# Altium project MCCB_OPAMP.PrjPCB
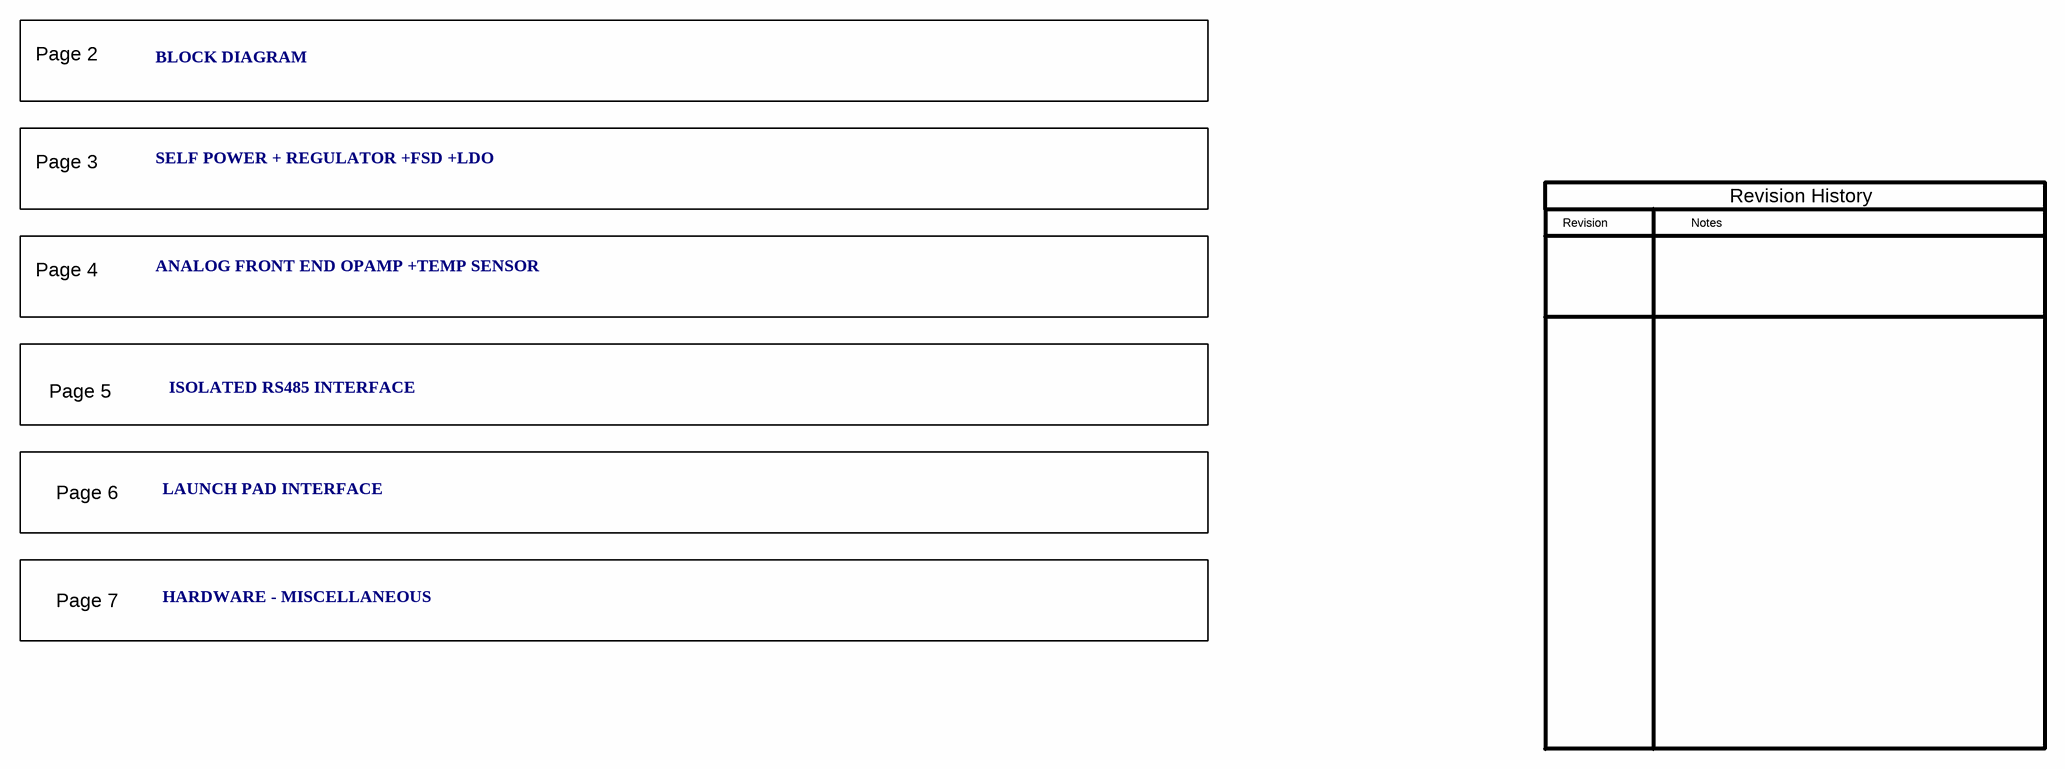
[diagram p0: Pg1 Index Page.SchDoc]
CopyrightYear: 2013; PCB_Layout: Who did the Layout?; PCB_Rev: E2; PRJ_Customer: Public Release; PRJ_Engineer: Enter name of project lead; PRJ_Number: TIDA-00128; PRJ_Title: TIDA-00128 OPAMP BASED MCCB ETU; SCH_Rev: E2; TechSupport: http://www.ti.com/support
7 sheets, 239 parts. Net scope: flat (ports and power ports of the same name join across sheets).
Board file: MCCB_OPAMP.PcbDoc
Sheets:
  Pg1 Index Page.SchDoc
  Pg2 Block Diagram.SchDoc
  Pg3.SchDoc
  Pg4.SchDoc
  Pg5.SchDoc
  Pg6.SchDoc
  Pg7 Hardware.SchDoc

## Sheet Pg1 Index Page.SchDoc
size 431 x 279 mm; Date: Not shown in title block; ApprovedBy: Not shown in title block; CheckedBy: Not shown in title block; Author: Not shown in title block; CompanyName: Not shown in title block; Engineer: Not shown in title block; Organization: Not shown in title block; Address1: Not shown in title block; Address2: Not shown in title block; Address3: Not shown in title block; Address4: Not shown in title block; DocumentNumber: 1; Revision: Use project parameter SCH_Rev; SheetNumber: 1; SheetTotal: 7; PageSetup: Record=PageOptions|CenterHorizontal=True|CenterVertical=True|PrintScale=1.00|XCorrection=1.00|YCorrection=1.00|PrintKind=0|BorderSize=5000000|LeftOffset=0|BottomOffset=0|Orientation=2|PaperLength=1000|PaperWidth=1000|Scale=100|PaperSource=15|PrintQuality=600|MediaType=1|DitherType=10|PaperKind=Letter|PrintScaleMode=1

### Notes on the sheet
- Page 2
- BLOCK DIAGRAM
- Page 3
- SELF POWER + REGULATOR +FSD +LDO
- Revision
- Notes
- Revision History
- Page 4
- ANALOG FRONT END OPAMP +TEMP SENSOR
- Page 5
- ISOLATED RS485 INTERFACE
- Page 6
- LAUNCH PAD INTERFACE
- Page 7
- HARDWARE - MISCELLANEOUS

## Sheet Pg2 Block Diagram.SchDoc
size 431 x 279 mm; Date: Not shown in title block; ApprovedBy: Not shown in title block; CheckedBy: Not shown in title block; Author: Not shown in title block; CompanyName: Not shown in title block; Engineer: Not shown in title block; Organization: Not shown in title block; Address1: Not shown in title block; Address2: Not shown in title block; Address3: Not shown in title block; Address4: Not shown in title block; DocumentNumber: 2; Revision: Use project parameter SCH_Rev; SheetNumber: 2; SheetTotal: 7; PageSetup: Record=PageOptions|CenterHorizontal=True|CenterVertical=True|PrintScale=1.00|XCorrection=1.00|YCorrection=1.00|PrintKind=0|BorderSize=5000000|LeftOffset=0|BottomOffset=0|Orientation=2|PaperLength=1000|PaperWidth=1000|Scale=100|PaperSource=15|PrintQuality=600|MediaType=1|DitherType=10|PaperKind=Letter|PrintScaleMode=1
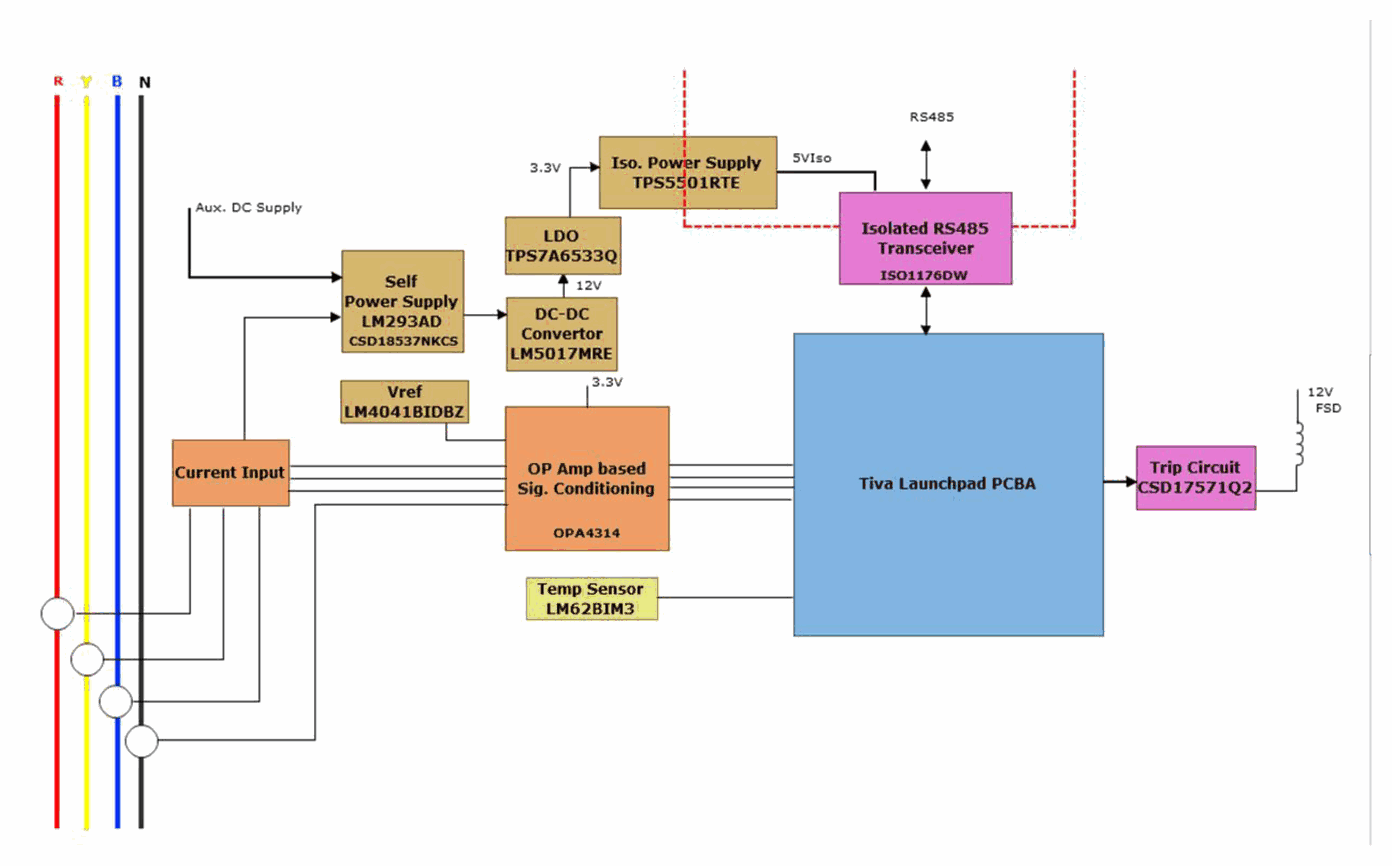
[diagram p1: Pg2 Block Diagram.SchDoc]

## Sheet Pg3.SchDoc
size 431 x 279 mm; Date: Not shown in title block; ApprovedBy: Not shown in title block; CheckedBy: Not shown in title block; Author: Not shown in title block; CompanyName: Not shown in title block; Engineer: Not shown in title block; Organization: Not shown in title block; Address1: Not shown in title block; Address2: Not shown in title block; Address3: Not shown in title block; Address4: Not shown in title block; DocumentNumber: 3; Revision: Use project parameter SCH_Rev; SheetNumber: 3; SheetTotal: 7; PageSetup: Record=PageOptions|CenterHorizontal=True|CenterVertical=True|PrintScale=1.00|XCorrection=1.00|YCorrection=1.00|PrintKind=0|BorderSize=5000000|LeftOffset=0|BottomOffset=0|Orientation=2|PaperLength=1000|PaperWidth=1000|Scale=100|PaperSource=15|PrintQuality=600|MediaType=1|DitherType=10|PaperKind=Letter|PrintScaleMode=1
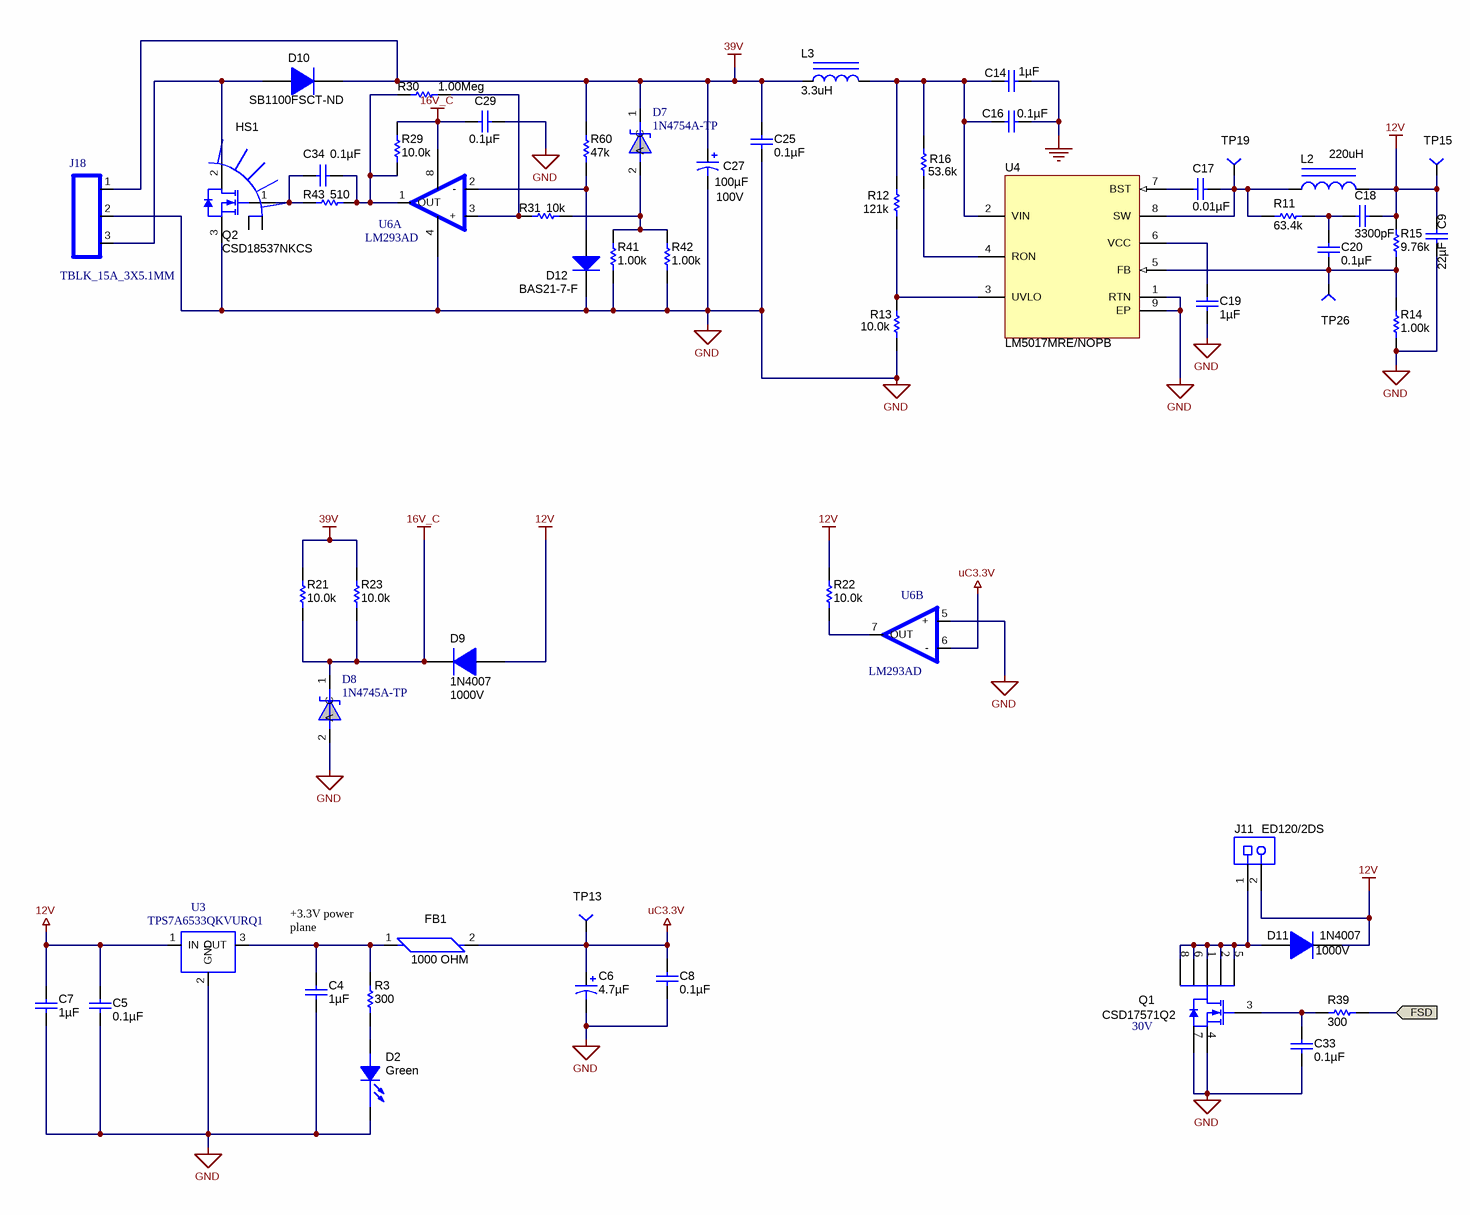
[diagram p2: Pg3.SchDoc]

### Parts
C4  ValueDisplayed: 1µF  [0603]  (hidden comment: C1608X7R1C105K)
C5  ValueDisplayed: 0.1µF  [0603]  (hidden comment: C0603C104K5RACTU)
C6  ValueDisplayed: 4.7µF  [6032-28]  (hidden comment: 293D475X9035C2TE3)
C7  ValueDisplayed: 1µF  [0603]  (hidden comment: C1608X7R1C105K)
C8  ValueDisplayed: 0.1µF  [0603]  (hidden comment: C0603C104K5RACTU)
C9  ValueDisplayed: 22µF  [1206]  (hidden comment: GRM31CR61C226KE15L)
C14  ValueDisplayed: 1µF  [1206]  (hidden comment: GRM31CR72A105KA01L)
C16  ValueDisplayed: 0.1µF  [0805_HV]  (hidden comment: C0805C104K1RACTU)
C17  ValueDisplayed: 0.01µF  [0603]  (hidden comment: C1608C0G1E103J)
C18  ValueDisplayed: 3300pF  [0603]  (hidden comment: C0603C332K5RACTU)
C19  ValueDisplayed: 1µF  [0603]  (hidden comment: C1608X5R1E105K080AC)
C20  ValueDisplayed: 0.1µF  [0603]  (hidden comment: 06033C104JAT2A)
C25  ValueDisplayed: 0.1µF  [0805_HV]  (hidden comment: C0805C104K1RACTU)
C27  ValueDisplayed: 100µF  Value2: 100V  [YXJ_1000x2000]  (hidden comment: 100YXJ100M10X20)
C29  ValueDisplayed: 0.1µF  [0603]  (hidden comment: C0603C104K5RACTU)
C33  ValueDisplayed: 0.1µF  [0603]  (hidden comment: 06033C104JAT2A)
C34  ValueDisplayed: 0.1µF  [0603]  (hidden comment: 06033C104JAT2A)
D2  value Green  [LED0603AA]  (hidden comment: LED_LG L29K-G2J1-24-Z)
D7  1N4754A-TP  [DO-41]
D8  1N4745A-TP  [DO-41]
D9  1N4007  value 1000V  [DO-41]
D10  SB1100FSCT-ND  [DO-41]
D11  1N4007  value 1000V  [DO-41]
D12  BAS21-7-F  [SOT-23]
FB1  1000 OHM  [0603]
HS1  HEATSINK_513102B02500G  [HEATSINK_513201]  (value not drawn)
J11  ED120/2DS  [CONN_ED120-2DS]
J18  TBLK_15A_3X5.1MM  [TB_3X5.1MM]
L2  value 220uH  [SRR7045]  (hidden comment: SRR7032-221M)
L3  value 3.3uH  [1210]  (hidden comment: B82422H1332K)
Q1  CSD17571Q2  value 30V  [SON_CSD17571Q2]
Q2  CSD18537NKCS  [TO-220AB]
R3  value 300  [0603]  (hidden comment: CRCW0603300RJNEA)
R11  value 63.4k  [0603]  (hidden comment: CRCW060363K4FKEA)
R12  value 121k  [0805_HV]  (hidden comment: RT0805BRD07121KL)
R13  value 10.0k  [0603]  (hidden comment: CRCW060310K0FKEA)
R14  value 1.00k  [0603]  (hidden comment: RC0603FR-071KL)
R15  value 9.76k  [0603]  (hidden comment: CRCW06039K76FKEA)
R16  value 53.6k  [0805_HV]  (hidden comment: RG2012P-5362-B-T5)
R21  value 10.0k  [1206]  (hidden comment: CRCW120610K0FKEA)
R22  value 10.0k  [0603]  (hidden comment: CRCW060310K0FKEA)
R23  value 10.0k  [1206]  (hidden comment: CRCW120610K0FKEA)
R29  value 10.0k  [1206]  (hidden comment: CRCW120610K0FKEA)
R30  value 1.00Meg  [0603]  (hidden comment: CRCW06031M00FKEA)
R31  value 10k  [0603]  (hidden comment: RNCF0603TKY10K0)
R39  value 300  [0603]  (hidden comment: CRCW0603300RJNEA)
R41  value 1.00k  [1206]  (hidden comment: CRCW12061K00FKEA)
R42  value 1.00k  [1206]  (hidden comment: CRCW12061K00FKEA)
R43  value 510  [0603]  (hidden comment: RG1608P-511-B-T5)
R60  value 47k  [0805_HV]  (hidden comment: ERJ-6GEYJ473V)
TP13  TP-040_RND  [TP-040_RND]  (value not drawn)
TP15  TP-040_RND  [TP-040_RND]  (value not drawn)
TP19  TP-040_RND  [TP-040_RND]  (value not drawn)
TP26  TP-040_RND  [TP-040_RND]  (value not drawn)
U3  TPS7A6533QKVURQ1  [KVU_1]
U4  LM5017MRE/NOPB  [DDA0008B_N]
U6  LM293AD  [SO8]  (parts A,B of 2)

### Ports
FSD (in)

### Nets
12V: C5.1 C7.1 C9.1 C18.1 D9.2(A) D11.1(K) J11.2 L2.2 R15.2 R22.2 TP15.1 U3.1(IN)
16V_C: C29.1 D8.1(C) D9.1(K) R21.1 R23.1 R29.1 U6.8(VCC)
39V: C25.1 C27.1(+) D7.1(C) D10.1(K) J18.1 L3.1 R21.2 R23.2 R60.2
GND: C4.2 C5.2 C6.2(-) C7.2 C8.2 C9.2 C14.1 C16.1 C19.2 C25.2 C27.2(-) C29.2 C33.2 D2.1(C) D8.2(A) D12.3(K) J18.2 Q1.4(S) Q1.7(S) Q2.3(S) R13.1 R14.1 R41.1 R42.1 U3.2(GND) U4.1(RTN) U4.9(EP) U6.4(GND) U6.5(+)
uC3.3V: C6.1(+) C8.1 FB1.2 TP13.1 U6.6(-)
FSD: R39.1 ; port FSD
NetC4_1: C4.1 FB1.1 R3.2 U3.3(OUT)
NetC14_2: C14.2 C16.2 L3.2 R12.2 R16.2 U4.2(VIN)
NetC17_1: C17.1 U4.7(BST)
NetC17_2: C17.2 L2.1 R11.1 TP19.1 U4.8(SW)
NetC18_2: C18.2 C20.2 R11.2
NetC19_1: C19.1 U4.6(VCC)
NetC20_1: C20.1 R14.2 R15.1 TP26.1 U4.5(FB)
NetC33_1: C33.1 Q1.3(G) R39.2
NetC34_1: C34.1 R29.2 R30.2 R43.1 U6.1(OUT)
NetC34_2: C34.2 Q2.1(G) R43.2
NetD2_2: D2.2(A) R3.1
NetD7_2: D7.2(A) R31.2 R41.2 R42.2
NetD10_2: D10.2(A) J18.3 Q2.2(D)
NetD11_2: D11.2(A) J11.1 Q1.1(D) Q1.2(D) Q1.5(D) Q1.6(D) Q1.8(D)
NetD12_1: D12.1(A) R60.1 U6.2(-)
NetR12_1: R12.1 R13.2 U4.3(UVLO)
NetR16_1: R16.1 U4.4(RON)
NetR22_1: R22.1 U6.7(OUT)
NetR30_1: R30.1 R31.1 U6.3(+)

Not connected (* = marked no-connect by the designer): HS1 1 2

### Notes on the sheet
- (near FB1) +3.3V power
  plane

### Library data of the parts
C4 C7 = C1608X7R1C105K: CAP, CERM, 1uF, 16V, +/-10%, X7R, 0603; Manufacturer: TDK; Polarized: N; CompType: Capacitor; U/M: EA; Cap_F: 0.000001; Tolerance_%: 10; ESR_Ohm: 0.0057; Value1: 0.0057 ohm; VDC_V: 16; TaMin_C: -55; TaMax_C: 125
C5 C8 C29 = C0603C104K5RACTU: CAP, CERM, 0.1uF, 50V, +/-10%, X7R, 0603; Manufacturer: Kemet; Polarized: N; CompType: Capacitor; U/M: EA; Cap_F: 0.0000001; Tolerance_%: 10; Value1: Unknown; VDC_V: 50; TaMin_C: -55; TaMax_C: 125
C6 = 293D475X9035C2TE3: CAP, TA, 4.7uF, 35V, +/-10%, 1.9 ohm, SMD; Manufacturer: Vishay-Sprague; Polarized: Y; CompType: Capacitor; U/M: EA; Cap_F: 0.0000047; Tolerance_%: 10; Value1: 1.9 ohm; VDC_V: 35; ESR_Ohm: 1.9; IRMS_A: 0.24; TaMin_C: -55; TaMax_C: 125; Cap_Case: C
C9 = GRM31CR61C226KE15L: CAP, CERM, 22uF, 16V, +/-10%, X5R, 1206; Manufacturer: MuRata; Polarized: N; CompType: Capacitor; U/M: EA; Cap_F: 0.000022; Tolerance_%: 10; Value1: Unknown; VDC_V: 16; TaMin_C: -55; TaMax_C: 85
C14 = GRM31CR72A105KA01L: CAP, CERM, 1uF, 100V, +/-10%, X7R, 1206; Manufacturer: MuRata; Polarized: N; CompType: Capacitor; U/M: EA; Cap_F: 0.000001; Tolerance_%: 10; Value1: Unknown; VDC_V: 100; TaMin_C: -55; TaMax_C: 125; Cap_Case: 2220
C16 C25 = C0805C104K1RACTU: CAP, CERM, 0.1uF, 100V, +/-10%, X7R, 0805; Manufacturer: Kemet; Polarized: N; CompType: Capacitor; U/M: EA; Cap_F: 0.0000001; Tolerance_%: 10; ESR_Ohm: 0.064; Value1: 0.064 ohm; VDC_V: 100; IRMS_A: 1.64; TaMin_C: -55; TaMax_C: 125; Cap_Case: 0805
C17 = C1608C0G1E103J: CAP, CERM, 0.01uF, 25V, +/-5%, C0G/NP0, 0603; Manufacturer: TDK; Polarized: N; CompType: Capacitor; U/M: EA; Cap_F: 0.00000001; Tolerance_%: 5; Value1: Unknown; VDC_V: 25; TaMin_C: -55; TaMax_C: 125
C18 = C0603C332K5RACTU: CAP, CERM, 3300pF, 50V, +/-10%, X7R, 0603; Manufacturer: Kemet; Polarized: N; CompType: Capacitor; U/M: EA; Cap_F: 0.0000000033; Tolerance_%: 10; Value1: Unknown; VDC_V: 50; TaMin_C: -55; TaMax_C: 125
C19 = C1608X5R1E105K080AC: CAP, CERM, 1uF, 25V, +/-10%, X5R, 0603; Manufacturer: TDK; Polarized: N; CompType: Capacitor; U/M: EA; Cap_F: 0.000001; Tolerance_%: 10; Value1: Unknown; VDC_V: 25; TaMin_C: -55; TaMax_C: 85
C20 C33 C34 = 06033C104JAT2A: CAP, CERM, 0.1uF, 25V, +/-5%, X7R, 0603; Manufacturer: AVX; Polarized: N; CompType: Capacitor; U/M: EA; Cap_F: 0.0000001; Tolerance_%: 5; ESR_Ohm: 0.05; Value1: 0.05 ohm; VDC_V: 25; TaMin_C: -55; TaMax_C: 125
C27 = 100YXJ100M10X20: CAP, AL, 100uF, 100V, +/-20%, 0.12 ohm, TH; Manufacturer: Rubycon; Polarized: Y; CompType: Capacitor; U/M: EA; Cap_F: 0.0001; Tolerance_%: 20; VDC_V: 100; ESR_Ohm: 0.12; IRMS_A: 1.04; TaMin_C: -40; TaMax_C: 105; Cap_Case: 10x20
D2 = LED_LG L29K-G2J1-24-Z: LED SmartLED Green 570NM; Manufacturer: OSRAM; SymbolCreator: x0120606
D7 = 1N4754A-TP: Diode, Zener, 39V, 1W, DO41; Manufacturer: Micro Commercial Co; Area: 54000
D8 = 1N4745A-TP: Diode, Zener, 16V, 1W, DO41; Manufacturer: Micro Commercial Co; Area: 54000
D9 D11 = 1N4007: Diode, P-N, 1000V, 1A, TH; Manufacturer: Fairchild Semiconductor; U/M: EA; Vf_V: 1.1; Value2: 1.1V; Io_A: 1; Vr_V: 1000; TJmax_C: 175; RJC_CperW: 50
D10 = 1N4007: Diode, P-N, 1100V, 1A, TH; Manufacturer: Fairchild Semiconductor; U/M: EA; Vf_V: 1.1; Value2: 1.1V; Io_A: 1; Vr_V: 1000; TJmax_C: 175; RJC_CperW: 50
D12 = BAS21-7-F: Diode, Switching, 200V, 0.2A, SOT-23; Manufacturer: Diodes Inc.; U/M: EA; Vf_V: 1.25; Value2: 1.25V; Io_A: 0.2; Vr_V: 200; TJmax_C: 150; RJC_CperW: 500
FB1 = MMZ1608B102C: FERRITE CHIP 1000 OHM 300MA 0603; Manufacturer: TDK Corporation; CompType: Ferrite Bead
HS1 = HEATSINK_513201: HEATSINK TO-220 W/PINS 1.5"TALL; Manufacturer: Aavid Thermalloy; area: 739800
J11 = ED120/2DS: TERMINAL BLOCK 5.08MM VERT 2POS, TH; Manufacturer: On-Shore Technology; SymbolCreator: a0412235; U/M: EA
J18 = TBLK_15A_3X5.1MM: Terminal Block, 3-pin, 15-A, 5.1mm; Manufacturer: OST; PartNumber: ED120/3DS; area: 212400; Value: ED120/3DS
L2 = IND_SRR7032-221M: Inductor, 220uH .30A SMD; Manufacturer: Bourns; Material: Ferrite
L3 = IND_B82422H1332K: Inductor, Chip, 3.3uH 770MA 1210 10%; Manufacturer: EPCOS Inc; Area: 28000
Q1 = CSD17571Q2: MOSFET, N-CH, 30V, 22A, SON 2X2 MM; Manufacturer: TEXAS INSTRUMENTS; CompType: POWER MOSFET
Q2 = CSD18537NKCS: MOSFET, N-CH, 60V, 50A, TO-220AB; Manufacturer: Texas Instruments; Alternate Manufacturer: None; ChType: N
R3 R39 = CRCW0603300RJNEA: RES, 300 ohm, 5%, 0.1W, 0603; Manufacturer: Vishay-Dale; CompType: Resistor; Value_Code: 300R; Tolerance_%: 5; Power_W: 0.1; VDC_V: 75; TempCo: 200 ppm/C; EIA_Code: E24; U/M: EA
R11 = CRCW060363K4FKEA: RES, 63.4k ohm, 1%, 0.1W, 0603; Manufacturer: Vishay-Dale; CompType: Resistor; Res_ohm: 63400; Value_Code: 63k4; Tolerance_%: 1; Power_W: 0.1; VDC_V: 75; TempCo: 100 ppm/C; EIA_Code: E96; U/M: EA
R12 = RT0805BRD07121KL: RES, 121k ohm, 0.1%, 0.125W, 0805; Manufacturer: Yageo America; CompType: Resistor; Res_ohm: 121000; Tolerance_%: 0.1; Power_W: 0.125; VDC_V: 150; TempCo: 25 ppm/C; EIA_Code: E192; U/M: EA
R13 R22 = CRCW060310K0FKEA: RES, 10.0k ohm, 1%, 0.1W, 0603; Manufacturer: Vishay-Dale; CompType: Resistor; Res_ohm: 10000; Value_Code: 10k0; Tolerance_%: 1; Power_W: 0.1; VDC_V: 75; TempCo: 100 ppm/C; EIA_Code: E96; U/M: EA
R14 = RC0603FR-071KL: RES, 1.00k ohm, 1%, 0.1W, 0603; Manufacturer: Yageo America; CompType: Resistor; Res_ohm: 1000; Value_Code: 1k00; Tolerance_%: 1; Power_W: 0.1; VDC_V: 150; TempCo: 200 ppm/C; EIA_Code: E96; U/M: EA
R15 = CRCW06039K76FKEA: RES, 9.76k ohm, 1%, 0.1W, 0603; Manufacturer: Vishay-Dale; CompType: Resistor; Res_ohm: 9760; Value_Code: 9k76; Tolerance_%: 1; Power_W: 0.1; VDC_V: 75; TempCo: 100 ppm/C; EIA_Code: E96; U/M: EA
R16 = RG2012P-5362-B-T5: RES, 53.6k ohm, 0.1%, 0.125W, 0805; Manufacturer: Susumu Co Ltd; CompType: Resistor; Res_ohm: 53600; Value_Code: 53k6; Tolerance_%: 0.1; Power_W: 0.125; VDC_V: 100; TempCo: 25 ppm/C; EIA_Code: E192; U/M: EA
R21 R23 R29 = CRCW120610K0FKEA: RES, 10.0k ohm, 1%, 0.25W, 1206; Manufacturer: Vishay-Dale; CompType: Resistor; Res_ohm: 10000; Value_Code: 10k0; Tolerance_%: 1; Power_W: 0.25; VDC_V: 200; TempCo: 100 ppm/C; EIA_Code: E96; U/M: EA
R30 = CRCW06031M00FKEA: RES, 1.00Meg ohm, 1%, 0.1W, 0603; Manufacturer: Vishay-Dale; CompType: Resistor; Res_ohm: 1000000; Value_Code: 1M00; Tolerance_%: 1; Power_W: 0.1; VDC_V: 75; TempCo: 100 ppm/C; EIA_Code: E96; U/M: EA
R31 = RNCF0603TKY10K0: RES, 10k ohm, 0.01%, 0.063W, 0603; Manufacturer: Stackpole Electronics Inc; CompType: Resistor; Res_ohm: 10000; Value_Code: 10k0; Tolerance_%: 0.01; Power_W: 0.063; VDC_V: 50; TempCo: 5 ppm/C; U/M: EA
R41 R42 = CRCW12061K00FKEA: RES, 1.00k ohm, 1%, 0.25W, 1206; Manufacturer: Vishay-Dale; CompType: Resistor; Res_ohm: 1000; Value_Code: 1k00; Tolerance_%: 1; Power_W: 0.25; VDC_V: 200; TempCo: 100 ppm/C; EIA_Code: E96; U/M: EA
R43 = RG1608P-511-B-T5: RES, 510 ohm, 0.1%, 0.1W, 0603; Manufacturer: Susumu Co Ltd; CompType: Resistor; Value_Code: 510R; Tolerance_%: 0.1; VDC_V: 75; TempCo: 25 ppm/C; U/M: EA
R60 = ERJ-6GEYJ473V: RES, 47k ohm, 5%, 0.125W, 0805; Manufacturer: Panasonic; CompType: Resistor; Res_ohm: 47000; Value_Code: 47k0; Tolerance_%: 5; Power_W: 0.125; VDC_V: 150; TempCo: 200 ppm/C; EIA_Code: E24; U/M: EA
TP13 TP15 TP19 TP26 = TP-040_RND: Test Point, O.040 Hole; Manufacturer: STD; Value: STD
U3 = TPS7A6533QKVURQ1: IC, 300-mA 40-V LOW-DROPOUT REGULATOR WITH 25-uA QUIESCENT CURRENT; Manufacturer: TI; Alternate Manufacturer: None; Area: 136210
U4 = LM5017MRE/NOPB: 100V, 600mA Constant On-Time Synchronous Buck Regulator, DDA0008B; Alternate Manufacturer: None; Manufacturer: Texas Instruments; SymbolCreator: a0412235; CompType: IC; U/M: EA
U6 = LM293AD: IC, Dual Differential Comparators, 2-36 Vin; Manufacturer: TI; Alternate Manufacturer: None; Area: 75900

## Sheet Pg4.SchDoc
size 431 x 279 mm; Date: Not shown in title block; ApprovedBy: Not shown in title block; CheckedBy: Not shown in title block; Author: Not shown in title block; CompanyName: Not shown in title block; Engineer: Not shown in title block; Organization: Not shown in title block; Address1: Not shown in title block; Address2: Not shown in title block; Address3: Not shown in title block; Address4: Not shown in title block; DocumentNumber: 4; Revision: Use project parameter SCH_Rev; SheetNumber: 4; SheetTotal: 7; PageSetup: Record=PageOptions|CenterHorizontal=True|CenterVertical=True|PrintScale=0.59|XCorrection=1.00|YCorrection=1.00|PrintKind=0|BorderSize=5000000|LeftOffset=0|BottomOffset=0|Orientation=2|PaperLength=1000|PaperWidth=1000|Scale=100|PaperSource=15|PrintQuality=600|MediaType=1|DitherType=10|PaperKind=Letter|PrintScaleMode=1
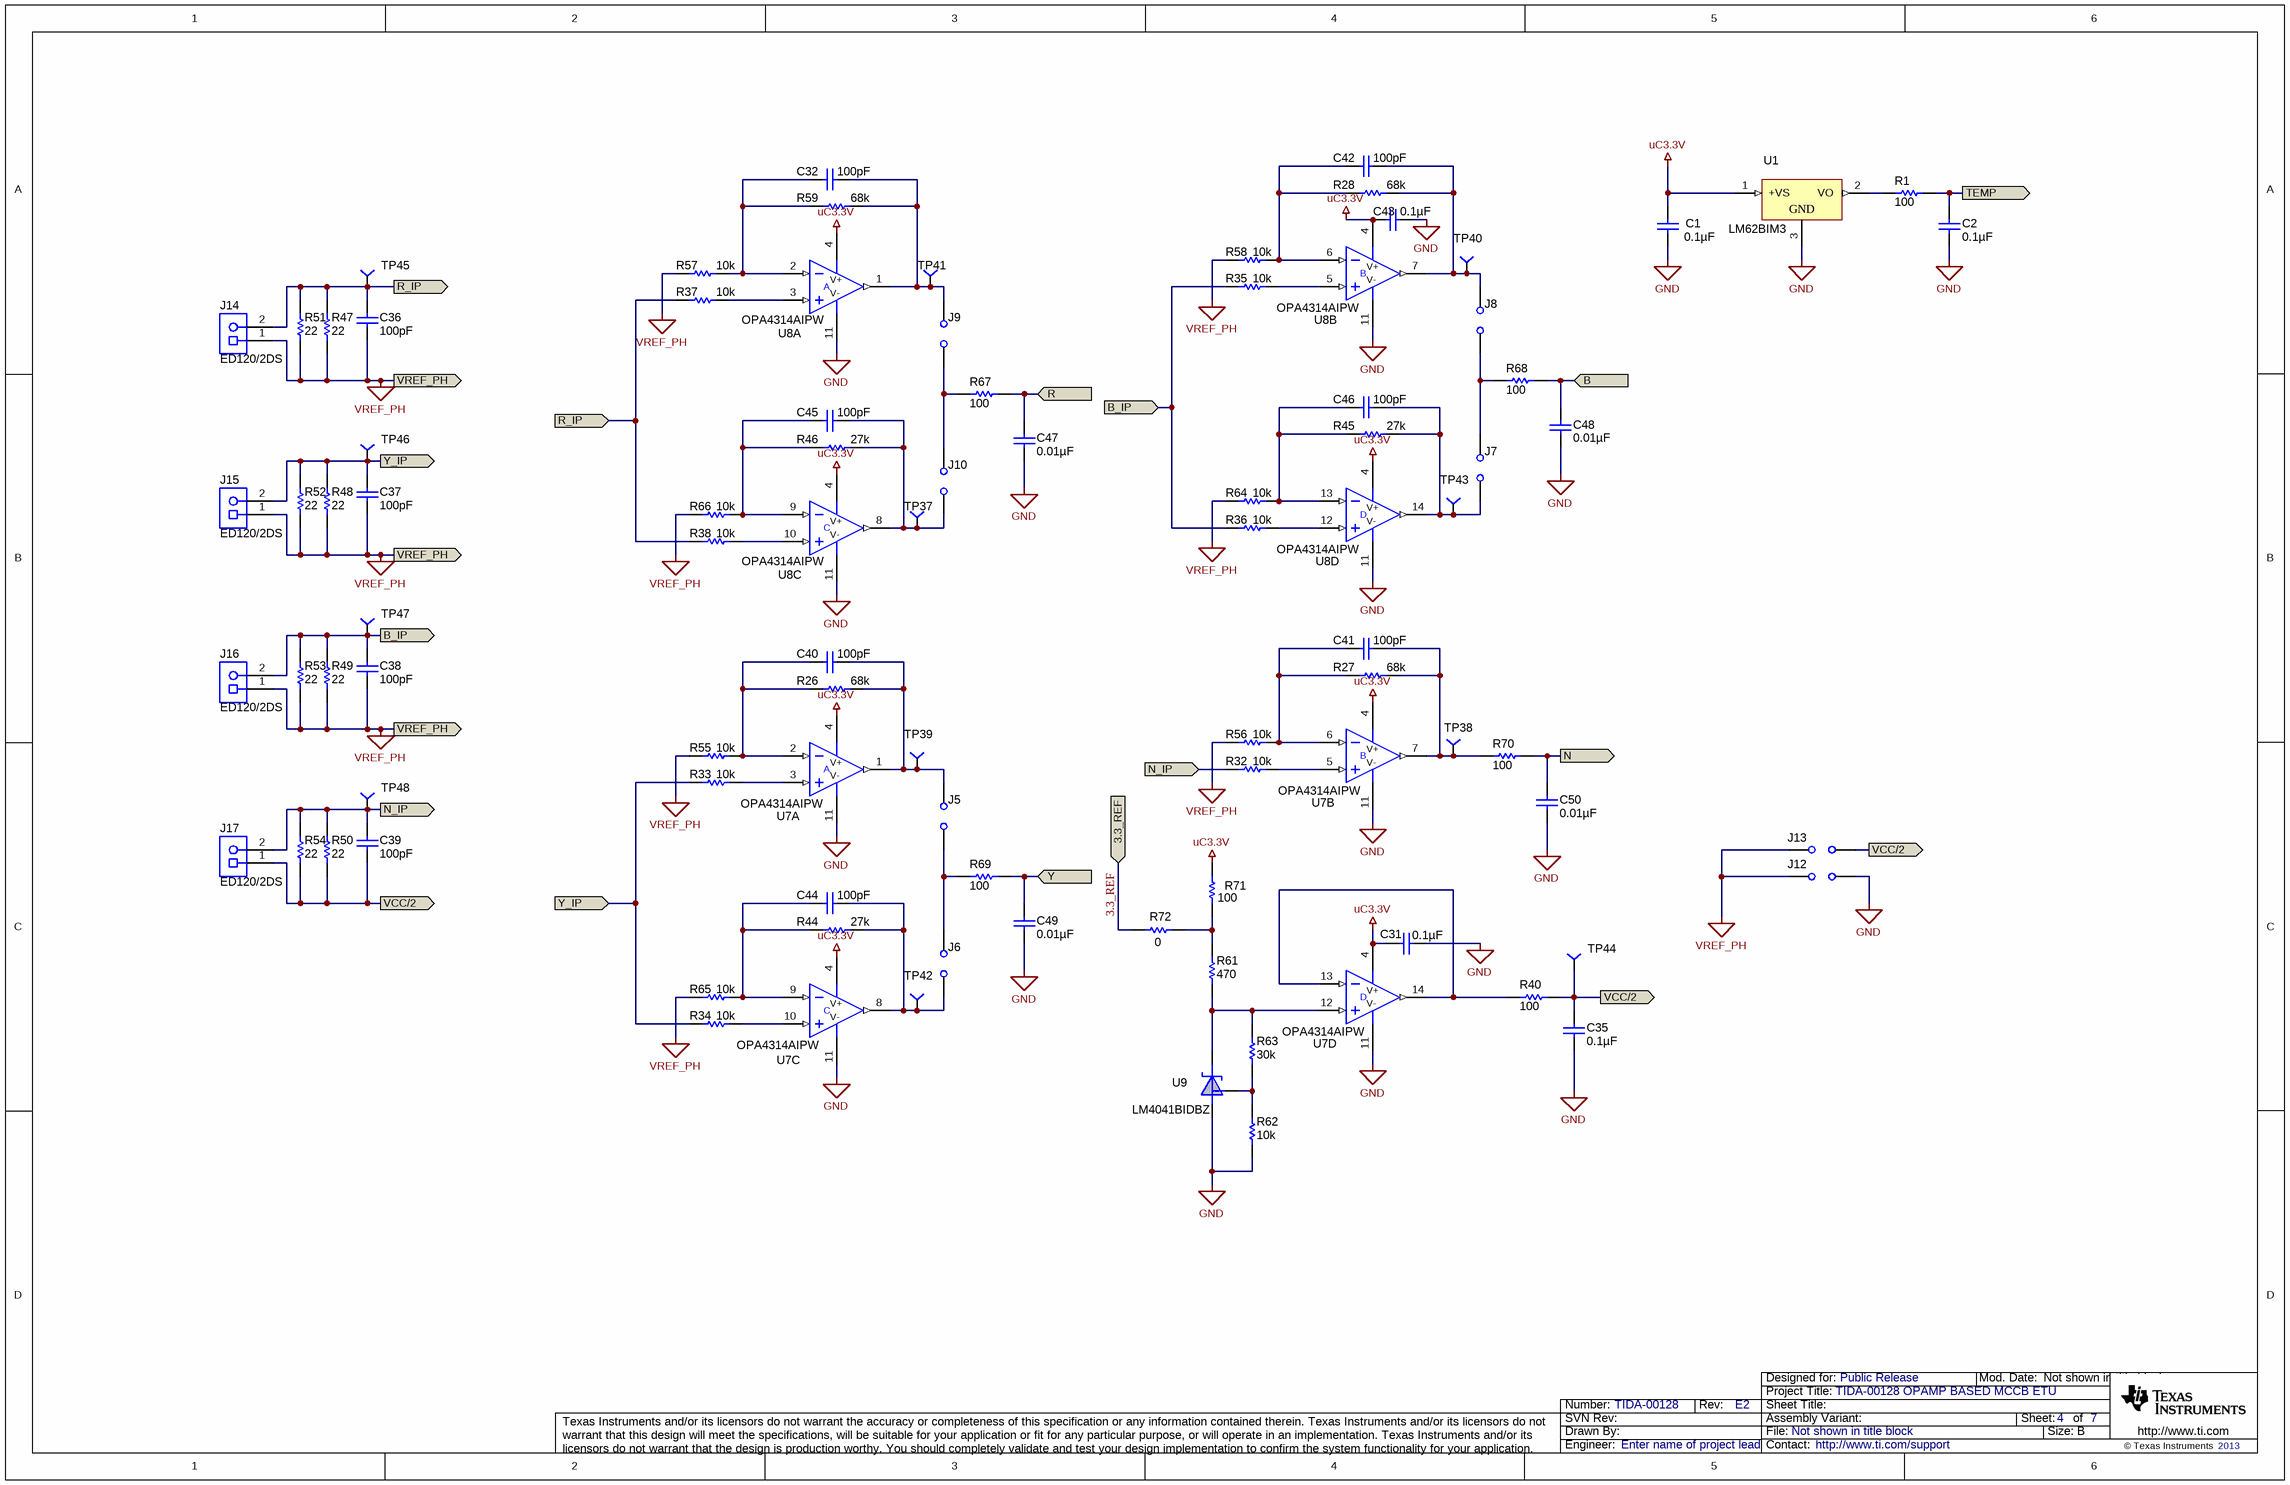
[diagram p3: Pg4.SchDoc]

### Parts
C1  ValueDisplayed: 0.1µF  [0603]  (hidden comment: 06033C104JAT2A)
C2  ValueDisplayed: 0.1µF  [0603]  (hidden comment: 06033C104JAT2A)
C31  ValueDisplayed: 0.1µF  [0603]  (hidden comment: 06033C104JAT2A)
C32  ValueDisplayed: 100pF  [0603]  (hidden comment: 06033C101KAT2A)
C35  ValueDisplayed: 0.1µF  [0603]  (hidden comment: 06033C104JAT2A)
C36  ValueDisplayed: 100pF  [0603]  (hidden comment: 06033C101KAT2A)
C37  ValueDisplayed: 100pF  [0603]  (hidden comment: 06033C101KAT2A)
C38  ValueDisplayed: 100pF  [0603]  (hidden comment: 06033C101KAT2A)
C39  ValueDisplayed: 100pF  [0603]  (hidden comment: 06033C101KAT2A)
C40  ValueDisplayed: 100pF  [0603]  (hidden comment: 06033C101KAT2A)
C41  ValueDisplayed: 100pF  [0603]  (hidden comment: 06033C101KAT2A)
C42  ValueDisplayed: 100pF  [0603]  (hidden comment: 06033C101KAT2A)
C43  ValueDisplayed: 0.1µF  [0603]  (hidden comment: 06033C104JAT2A)
C44  ValueDisplayed: 100pF  [0603]  (hidden comment: 06033C101KAT2A)
C45  ValueDisplayed: 100pF  [0603]  (hidden comment: 06033C101KAT2A)
C46  ValueDisplayed: 100pF  [0603]  (hidden comment: 06033C101KAT2A)
C47  ValueDisplayed: 0.01µF  [0603]  (hidden comment: C1608C0G1E103J)
C48  ValueDisplayed: 0.01µF  [0603]  (hidden comment: C1608C0G1E103J)
C49  ValueDisplayed: 0.01µF  [0603]  (hidden comment: C1608C0G1E103J)
C50  ValueDisplayed: 0.01µF  [0603]  (hidden comment: C1608C0G1E103J)
J5  JUMPER_2X100MIL  [HDR100_1X2]  (value not drawn)
J6  JUMPER_2X100MIL  [HDR100_1X2]  (value not drawn)
J7  JUMPER_2X100MIL  [HDR100_1X2]  (value not drawn)
J8  JUMPER_2X100MIL  [HDR100_1X2]  (value not drawn)
J9  JUMPER_2X100MIL  [HDR100_1X2]  (value not drawn)
J10  JUMPER_2X100MIL  [HDR100_1X2]  (value not drawn)
J12  JUMPER_2X100MIL  [HDR100_1X2]  (value not drawn)
J13  JUMPER_2X100MIL  [HDR100_1X2]  (value not drawn)
J14  ED120/2DS  [CONN_ED120-2DS]
J15  ED120/2DS  [CONN_ED120-2DS]
J16  ED120/2DS  [CONN_ED120-2DS]
J17  ED120/2DS  [CONN_ED120-2DS]
R1  value 100  [0603]  (hidden comment: CRCW0603100RFKEA)
R26  value 68k  [0603]  (hidden comment: CRCW060368K0JNEA)
R27  value 68k  [0603]  (hidden comment: CRCW060368K0JNEA)
R28  value 68k  [0603]  (hidden comment: CRCW060368K0JNEA)
R32  value 10k  [0603]  (hidden comment: RNCF0603TKY10K0)
R33  value 10k  [0603]  (hidden comment: RNCF0603TKY10K0)
R34  value 10k  [0603]  (hidden comment: RNCF0603TKY10K0)
R35  value 10k  [0603]  (hidden comment: RNCF0603TKY10K0)
R36  value 10k  [0603]  (hidden comment: RNCF0603TKY10K0)
R37  value 10k  [0603]  (hidden comment: RNCF0603TKY10K0)
R38  value 10k  [0603]  (hidden comment: RNCF0603TKY10K0)
R40  value 100  [0603]  (hidden comment: CRCW0603100RFKEA)
R44  value 27k  [0603]  (hidden comment: RC0603JR-0727KL)
R45  value 27k  [0603]  (hidden comment: RC0603JR-0727KL)
R46  value 27k  [0603]  (hidden comment: RC0603JR-0727KL)
R47  value 22  [1206]  (hidden comment: CRCW120622R0JNEA)
R48  value 22  [1206]  (hidden comment: CRCW120622R0JNEA)
R49  value 22  [1206]  (hidden comment: CRCW120622R0JNEA)
R50  value 22  [1206]  (hidden comment: CRCW120622R0JNEA)
R51  value 22  [1206]  (hidden comment: CRCW120622R0JNEA)
R52  value 22  [1206]  (hidden comment: CRCW120622R0JNEA)
R53  value 22  [1206]  (hidden comment: CRCW120622R0JNEA)
R54  value 22  [1206]  (hidden comment: CRCW120622R0JNEA)
R55  value 10k  [0603]  (hidden comment: RNCF0603TKY10K0)
R56  value 10k  [0603]  (hidden comment: RNCF0603TKY10K0)
R57  value 10k  [0603]  (hidden comment: RNCF0603TKY10K0)
R58  value 10k  [0603]  (hidden comment: RNCF0603TKY10K0)
R59  value 68k  [0603]  (hidden comment: CRCW060368K0JNEA)
R61  value 470  [0603]  (hidden comment: CRCW0603470RJNEA)
R62  value 10k  [0603]  (hidden comment: RNCF0603TKY10K0)
R63  value 30k  [0603]  (hidden comment: CRCW060330K0JNEA)
R64  value 10k  [0603]  (hidden comment: RNCF0603TKY10K0)
R65  value 10k  [0603]  (hidden comment: RNCF0603TKY10K0)
R66  value 10k  [0603]  (hidden comment: RNCF0603TKY10K0)
R67  value 100  [0603]  (hidden comment: CRCW0603100RFKEA)
R68  value 100  [0603]  (hidden comment: CRCW0603100RFKEA)
R69  value 100  [0603]  (hidden comment: CRCW0603100RFKEA)
R70  value 100  [0603]  (hidden comment: CRCW0603100RFKEA)
R71  value 100  [0603]  (hidden comment: CRCW0603100RFKEA)
R72  value 0  [0603]  (hidden comment: CRCW06030000Z0EA)
TP37  TP-040_RND  [TP-040_RND]  (value not drawn)
TP38  TP-040_RND  [TP-040_RND]  (value not drawn)
TP39  TP-040_RND  [TP-040_RND]  (value not drawn)
TP40  TP-040_RND  [TP-040_RND]  (value not drawn)
TP41  TP-040_RND  [TP-040_RND]  (value not drawn)
TP42  TP-040_RND  [TP-040_RND]  (value not drawn)
TP43  TP-040_RND  [TP-040_RND]  (value not drawn)
TP44  TP-040_RND  [TP-040_RND]  (value not drawn)
TP45  TP-040_RND  [TP-040_RND]  (value not drawn)
TP46  TP-040_RND  [TP-040_RND]  (value not drawn)
TP47  TP-040_RND  [TP-040_RND]  (value not drawn)
TP48  TP-040_RND  [TP-040_RND]  (value not drawn)
U1  LM62BIM3  [MF03A_N]
U7  OPA4314AIPW  [PW0014A_N]  (parts A,B,C,D of 4)
U8  OPA4314AIPW  [PW0014A_N]  (parts A,B,C,D of 4)
U9  LM4041BIDBZ  [SOT-23]

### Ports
3.3_REF (in), B (in), B_IP (in), B_IP (out), N (out), N_IP (in), N_IP (out), R (in), R_IP (in), R_IP (out), TEMP (out), VCC/2 (out), VREF_PH (out), Y (in), Y_IP (in), Y_IP (out)

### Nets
GND: C1.2 C2.1 C31.1 C35.1 C43.1 C47.1 C48.1 C49.1 C50.1 J12.2 R62.1 U1.3(GND) U7.11(V-) U8.11(V-) U9.3(A)
uC3.3V: C1.1 C31.2 C43.2 R71.1 U1.1(+VS) U7.4(V+) U8.4(V+)
VREF_PH: C36.2 C37.2 C38.2 J12.1 J13.1 J14.1 J15.1 J16.1 R47.1 R48.1 R49.1 R51.1 R52.1 R53.1 R55.1 R56.1 R57.1 R58.1 R64.1 R65.1 R66.1 ; port VREF_PH
3.3_REF: R72.1 ; port 3.3_REF
B: C48.2 R68.2 ; port B
B_IP: C38.1 J16.2 R35.1 R36.1 R49.2 R53.2 TP47.1 ; port B_IP
N: C50.2 R70.2 ; port N
N_IP: C39.1 J17.2 R32.1 R50.2 R54.2 TP48.1 ; port N_IP
R: C47.2 R67.2 ; port R
R_IP: C36.1 J14.2 R37.1 R38.1 R47.2 R51.2 TP45.1 ; port R_IP
TEMP: C2.2 R1.2 ; port TEMP
VCC/2: C35.2 C39.2 J13.2 J17.1 R40.2 R50.1 R54.1 TP44.1 ; port VCC/2
Y: C49.2 R69.2 ; port Y
Y_IP: C37.1 J15.2 R33.1 R34.1 R48.2 R52.2 TP46.1 ; port Y_IP
NetC32_1: C32.1 R57.2 R59.1 U8.2(IN-)
NetC32_2: C32.2 J9.2 R59.2 TP41.1 U8.1(OUT)
NetC40_1: C40.1 R26.1 R55.2 U7.2(IN-)
NetC40_2: C40.2 J5.2 R26.2 TP39.1 U7.1(OUT)
NetC41_1: C41.1 R27.1 R56.2 U7.6(IN-)
NetC41_2: C41.2 R27.2 R70.1 TP38.1 U7.7(OUT)
NetC42_1: C42.1 R28.1 R58.2 U8.6(IN-)
NetC42_2: C42.2 J8.2 R28.2 TP40.1 U8.7(OUT)
NetC44_1: C44.1 R44.1 R65.2 U7.9(IN-)
NetC44_2: C44.2 J6.1 R44.2 TP42.1 U7.8(OUT)
NetC45_1: C45.1 R46.1 R66.2 U8.9(IN-)
NetC45_2: C45.2 J10.1 R46.2 TP37.1 U8.8(OUT)
NetC46_1: C46.1 R45.1 R64.2 U8.13(IN-)
NetC46_2: C46.2 J7.1 R45.2 TP43.1 U8.14(OUT)
NetJ5_1: J5.1 J6.2 R69.1
NetJ7_2: J7.2 J8.1 R68.1
NetJ9_1: J9.1 J10.2 R67.1
NetR1_1: R1.1 U1.2(VO)
NetR32_2: R32.2 U7.5(IN+)
NetR33_2: R33.2 U7.3(IN+)
NetR34_2: R34.2 U7.10(IN+)
NetR35_2: R35.2 U8.5(IN+)
NetR36_2: R36.2 U8.12(IN+)
NetR37_2: R37.2 U8.3(IN+)
NetR38_2: R38.2 U8.10(IN+)
NetR40_1: R40.1 U7.13(IN-) U7.14(OUT)
NetR61_1: R61.1 R63.2 U7.12(IN+) U9.2(C)
NetR61_2: R61.2 R71.2 R72.2
NetR62_2: R62.2 R63.1 U9.1(FB)

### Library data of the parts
C1 C2 C31 C35 C43 = 06033C104JAT2A: as C20 on sheet Pg3
C32 C36-C42 C44-C46 = 06033C101KAT2A: CAP, CERM, 100pF, 25V, +/-10%, X7R, 0603; Manufacturer: AVX; Polarized: N; CompType: Capacitor; U/M: EA; Cap_F: 0.0000000001; Tolerance_%: 10; Value1: Unknown; VDC_V: 25; TaMin_C: -55; TaMax_C: 125
C47-C50 = C1608C0G1E103J: as C17 on sheet Pg3
J5-J10 J12 J13 = JUMPER_2X100MIL: Header, Male 2-pin, 100mil spacing,; Manufacturer: Sullins; PartNumber: PEC02SAAN; area: 20000; Value: PEC02SAAN
J14-J17 = ED120/2DS: as J11 on sheet Pg3
R1 R40 R67-R71 = CRCW0603100RFKEA: RES, 100 ohm, 1%, 0.1W, 0603; Manufacturer: Vishay-Dale; CompType: Resistor; Value_Code: 100R; Tolerance_%: 1; Power_W: 0.1; VDC_V: 75; TempCo: 100 ppm/C; EIA_Code: E96; U/M: EA
R26-R28 R59 = CRCW060368K0JNEA: RES, 68k ohm, 5%, 0.1W, 0603; Manufacturer: Vishay-Dale; CompType: Resistor; Res_ohm: 68000; Value_Code: 68k0; Tolerance_%: 5; Power_W: 0.1; VDC_V: 75; TempCo: 200 ppm/C; EIA_Code: E24; U/M: EA
R32-R38 R55-R58 R62 R64-R66 = RNCF0603TKY10K0: as R31 on sheet Pg3
R44-R46 = RC0603JR-0727KL: RES, 27k ohm, 5%, 0.1W, 0603; Manufacturer: Yageo America; CompType: Resistor; Res_ohm: 27000; Value_Code: 27k0; Tolerance_%: 5; Power_W: 0.1; VDC_V: 50; TempCo: 100 ppm/C; EIA_Code: E24; U/M: EA
R47-R54 = CRCW120622R0JNEA: RES, 22 ohm, 5%, 0.25W, 1206; Manufacturer: Vishay-Dale; CompType: Resistor; Value_Code: 22R0; Tolerance_%: 5; Power_W: 0.25; VDC_V: 200; TempCo: 200 ppm/C; EIA_Code: E24; U/M: EA
R61 = CRCW0603470RJNEA: RES, 470 ohm, 5%, 0.1W, 0603; Manufacturer: Vishay-Dale; CompType: Resistor; Value_Code: 470R; Tolerance_%: 5; Power_W: 0.1; VDC_V: 75; TempCo: 200 ppm/C; EIA_Code: E24; U/M: EA
R63 = CRCW060330K0JNEA: RES, 30k ohm, 5%, 0.1W, 0603; Manufacturer: Vishay-Dale; CompType: Resistor; Res_ohm: 30000; Value_Code: 30k0; Tolerance_%: 5; Power_W: 0.1; VDC_V: 75; TempCo: 200 ppm/C; EIA_Code: E24; U/M: EA
R72 = CRCW06030000Z0EA: RES, 0 ohm, 5%, 0.1W, 0603; Manufacturer: Vishay-Dale; CompType: Resistor; Value_Code: 0000; Tolerance_%: 5; Power_W: 0.1; VDC_V: 75; TempCo: 200 ppm/C; EIA_Code: E24; U/M: EA
TP37-TP48 = TP-040_RND: as TP13 on sheet Pg3
U1 = LM62BIM3: 2.7V, 15.6mV/°C, Temperature Sensor, 3-pin SOT-23; Manufacturer: National Semiconductor; PackageTopMarking: T7B*XTT; PowerWise: N; CompType: Temp Sensor IC
U7 U8 = LMV324IPW: LOW-VOLTAGE RAIL-TO-RAIL OUTPUT OPERATIONAL AMPLIFIERS, PW0014A; Alternate Manufacturer: None; Manufacturer: Texas Instruments; SymbolCreator: a0411947; CompType: IC; U/M: EA
U9 = LM4041BIDBZ: IC, Micropower Shunt Voltage Reference 100 ppm/°C, 45µA-12mA,  Adjustable; Manufacturer: TI; Alternate Manufacturer: None; Area: 25500

## Sheet Pg5.SchDoc
size 431 x 279 mm; Date: Not shown in title block; ApprovedBy: Not shown in title block; CheckedBy: Not shown in title block; Author: Not shown in title block; CompanyName: Not shown in title block; Engineer: Not shown in title block; Organization: Not shown in title block; Address1: Not shown in title block; Address2: Not shown in title block; Address3: Not shown in title block; Address4: Not shown in title block; DocumentNumber: 5; Revision: Use project parameter SCH_Rev; SheetNumber: 5; SheetTotal: 7; PageSetup: Record=PageOptions|CenterHorizontal=True|CenterVertical=True|PrintScale=1.00|XCorrection=1.00|YCorrection=1.00|PrintKind=0|BorderSize=5000000|LeftOffset=0|BottomOffset=0|Orientation=2|PaperLength=1000|PaperWidth=1000|Scale=100|PaperSource=15|PrintQuality=600|MediaType=1|DitherType=10|PaperKind=Letter|PrintScaleMode=1
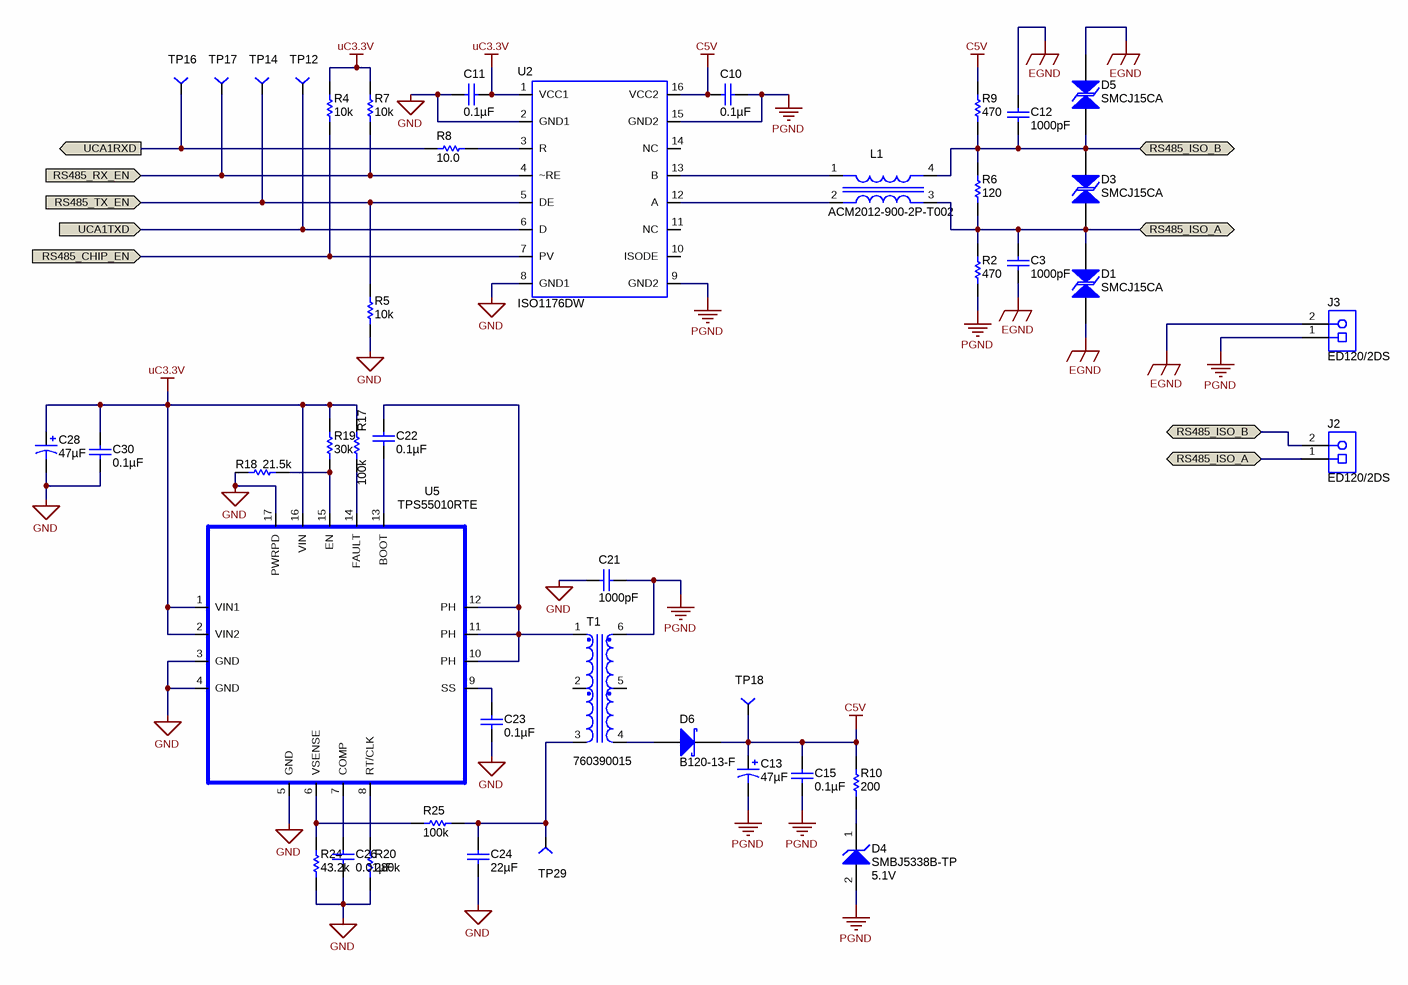
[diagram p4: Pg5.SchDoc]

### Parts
C3  ValueDisplayed: 1000pF  [1206]  (hidden comment: CC1206KKX7RCBB102)
C10  ValueDisplayed: 0.1µF  [0603]  (hidden comment: 06033C104JAT2A)
C11  ValueDisplayed: 0.1µF  [0603]  (hidden comment: 06033C104JAT2A)
C12  ValueDisplayed: 1000pF  [1206]  (hidden comment: CC1206KKX7RCBB102)
C13  ValueDisplayed: 47µF  [7343-43]  (hidden comment: T495X476K035ATE300)
C15  ValueDisplayed: 0.1µF  [0603]  (hidden comment: 06033C104JAT2A)
C21  ValueDisplayed: 1000pF  [1206]  (hidden comment: CC1206KKX7RCBB102)
C22  ValueDisplayed: 0.1µF  [0603]  (hidden comment: 06033C104JAT2A)
C23  ValueDisplayed: 0.1µF  [0603]  (hidden comment: 06033C104JAT2A)
C24  ValueDisplayed: 22µF  [1206]  (hidden comment: 1206YD226MAT2A)
C26  ValueDisplayed: 0.01µF  [0603]  (hidden comment: C1608C0G1E103J)
C28  ValueDisplayed: 47µF  [7343-43]  (hidden comment: T495X476K035ATE300)
C30  ValueDisplayed: 0.1µF  [0603]  (hidden comment: 06033C104JAT2A)
D1  SMCJ15CA  [SMC]
D3  SMCJ15CA  [SMC]
D4  SMBJ5338B-TP  value 5.1V  [SMB]
D5  SMCJ15CA  [SMC]
D6  B120-13-F  [SMA]
J2  ED120/2DS  [CONN_ED120-2DS]
J3  ED120/2DS  [CONN_ED120-2DS]
L1  ACM2012-900-2P-T002  [IND_0805-4P]
R2  value 470  [0805_HV]  (hidden comment: CRCW0805470RFKEA)
R4  value 10k  [0603]  (hidden comment: CRCW060310K0JNEA)
R5  value 10k  [0603]  (hidden comment: CRCW060310K0JNEA)
R6  value 120  [0805_HV]  (hidden comment: CRCW0805120RJNEA)
R7  value 10k  [0603]  (hidden comment: CRCW060310K0JNEA)
R8  value 10.0  [0603]  (hidden comment: CRCW060310R0FKEA)
R9  value 470  [0805_HV]  (hidden comment: CRCW0805470RFKEA)
R10  value 200  [0603]  (hidden comment: CRCW0603200RFKEA)
R17  value 100k  [0603]  (hidden comment: CRCW0603100KFKEA)
R18  value 21.5k  [0603]  (hidden comment: CRCW060321K5FKEA)
R19  value 30k  [0603]  (hidden comment: CRCW060330K0JNEA)
R20  value 280k  [0603]  (hidden comment: CRCW0603280KFKEA)
R24  value 43.2k  [0603]  (hidden comment: CRCW060343K2FKEA)
R25  value 100k  [0603]  (hidden comment: CRCW0603100KFKEA)
T1  760390015  [760390015]
TP12  TP-040_RND  [TP-040_RND]  (value not drawn)
TP14  TP-040_RND  [TP-040_RND]  (value not drawn)
TP16  TP-040_RND  [TP-040_RND]  (value not drawn)
TP17  TP-040_RND  [TP-040_RND]  (value not drawn)
TP18  TP-040_RND  [TP-040_RND]  (value not drawn)
TP29  TP-040_RND  [TP-040_RND]  (value not drawn)
U2  ISO1176DW  [DW0016A_N]
U5  TPS55010RTE  [RTE-16]

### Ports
RS485_CHIP_EN (in), RS485_ISO_A (bidir), RS485_ISO_B (bidir), RS485_RX_EN (in), RS485_TX_EN (in), UCA1RXD (out), UCA1TXD (in)

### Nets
C5V: C10.2 C13.1(+) C15.1 D6.1(K) R9.2 R10.2 TP18.1 U2.16(VCC2)
EGND: C3.2 C12.1 D1.1 D5.2 J3.2
GND: C11.1 C21.2 C23.1 C24.2 C26.2 C28.2(-) C30.2 R5.1 R18.1 R20.1 R24.1 U2.2(GND1) U2.8(GND1) U5.3(GND) U5.4(GND) U5.5(GND) U5.17(PWRPD)
PGND: C10.1 C13.2(-) C15.2 C21.1 D4.2(A) J3.1 R2.1 T1.6 U2.9(GND2) U2.15(GND2)
uC3.3V: C11.2 C28.1(+) C30.1 R4.2 R7.2 R17.2 R19.2 U2.1(VCC1) U5.1(VIN1) U5.2(VIN2) U5.16(VIN)
RS485_CHIP_EN: R4.1 U2.7(PV) ; port RS485_CHIP_EN
RS485_ISO_A: C3.1 D1.2 D3.1 J2.1 L1.3 R2.2 R6.1 ; port RS485_ISO_A
RS485_ISO_B: C12.2 D3.2 D5.1 J2.2 L1.4 R6.2 R9.1 ; port RS485_ISO_B
RS485_RX_EN: R7.1 TP17.1 U2.4(~RE) ; port RS485_RX_EN
RS485_TX_EN: R5.2 TP14.1 U2.5(DE) ; port RS485_TX_EN
UCA1RXD: R8.1 TP16.1 ; port UCA1RXD
UCA1TXD: TP12.1 U2.6(D) ; port UCA1TXD
NetC22_1: C22.1 T1.1 U5.10(PH) U5.11(PH) U5.12(PH)
NetC22_2: C22.2 U5.13(BOOT)
NetC23_2: C23.2 U5.9(SS)
NetC24_1: C24.1 R25.1 T1.3 TP29.1
NetC26_1: C26.1 U5.7(COMP)
NetD4_1: D4.1(K) R10.1
NetD6_2: D6.2(A) T1.4
NetL1_1: L1.1 U2.13(B)
NetL1_2: L1.2 U2.12(A)
NetR8_2: R8.2 U2.3(R)
NetR17_1: R17.1 U5.14(FAULT)
NetR18_2: R18.2 R19.1 U5.15(EN)
NetR20_2: R20.2 U5.8(RT/CLK)
NetR24_2: R24.2 R25.2 U5.6(VSENSE)

Not connected (* = marked no-connect by the designer): T1 2 5; U2 10(ISODE) 11(NC) 14(NC)

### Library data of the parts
C3 C12 C21 = CC1206KKX7RCBB102: CAP, CERM, 1000pF, 1000V, +/-10%, X7R, 1206; Manufacturer: Yageo America; Polarized: N; CompType: Capacitor; U/M: EA; Cap_F: 0.000000001; Tolerance_%: 10; Value1: Unknown; VDC_V: 1000; TaMin_C: -55; TaMax_C: 125
C10 C11 C15 C22 C23 C30 = 06033C104JAT2A: as C20 on sheet Pg3
C13 C28 = T495X476K035ATE300: CAP, TA, 47uF, 35V, +/-10%, 0.3 ohm, SMD; Manufacturer: Kemet; Polarized: Y; CompType: Capacitor; U/M: EA; Cap_F: 0.000047; Tolerance_%: 10; Value1: 0.3 ohm; VDC_V: 35; ESR_Ohm: 0.3; IRMS_A: 0.667; TaMin_C: -55; TaMax_C: 125; Cap_Case: X
C24 = 1206YD226MAT2A: CAP, CERM, 22uF, 16V, +/-20%, X5R, 1206; Manufacturer: AVX; Polarized: N; CompType: Capacitor; U/M: EA; Cap_F: 0.000022; Tolerance_%: 20; Value1: Unknown; VDC_V: 16; TaMin_C: -55; TaMax_C: 85
C26 = C1608C0G1E103J: as C17 on sheet Pg3
D1 D3 D5 = SMCJ15CA: Diode, TVS 15V 1500W BIDIR 5% SMC; Manufacturer: Littelfuse Inc; Power_W: 1500
D4 = SMBJ5338B-TP: Diode, Zener, 5.1V, 5W, SMB; Manufacturer: Micro Commercial Components; U/M: EA; Power_W: 5; Vz_V: 5.1; RJA_CperW: 25
D6 = B120-13-F: Diode, Schottky, 20V, 1A, SMA; Manufacturer: Diodes Inc.; U/M: EA; Vf_V: 0.5; Value2: 0.5V; Io_A: 1; Vr_V: 20; TJmax_C: 150
J2 J3 = ED120/2DS: as J11 on sheet Pg3
L1 = IND_ACM2012_SERIES: Inductor, Common Mode Filter SMD; Manufacturer: TDK; Area: 8.13 mm; Value: xx uH
R2 R9 = CRCW0805470RFKEA: RES, 470 ohm, 1%, 0.125W, 0805; Manufacturer: Vishay-Dale; CompType: Resistor; Value_Code: 470R; Tolerance_%: 1; Power_W: 0.125; VDC_V: 150; TempCo: 100 ppm/C; U/M: EA
R4 R5 R7 = CRCW060310K0JNEA: RES, 10k ohm, 5%, 0.1W, 0603; Manufacturer: Vishay-Dale; CompType: Resistor; Res_ohm: 10000; Value_Code: 10k0; Tolerance_%: 5; Power_W: 0.1; VDC_V: 75; TempCo: 200 ppm/C; EIA_Code: E24; U/M: EA
R6 = CRCW0805120RJNEA: RES, 120 ohm, 5%, 0.125W, 0805; Manufacturer: Vishay-Dale; CompType: Resistor; Value_Code: 120R; Tolerance_%: 5; Power_W: 0.125; VDC_V: 150; TempCo: 200 ppm/C; EIA_Code: E24; U/M: EA
R8 = CRCW060310R0FKEA: RES, 10.0 ohm, 1%, 0.1W, 0603; Manufacturer: Vishay-Dale; CompType: Resistor; Res_ohm: 10; Value_Code: 10R0; Tolerance_%: 1; Power_W: 0.1; VDC_V: 75; TempCo: 100 ppm/C; EIA_Code: E96; U/M: EA
R10 = CRCW0603200RFKEA: RES, 200 ohm, 1%, 0.1W, 0603; Manufacturer: Vishay-Dale; CompType: Resistor; Value_Code: 200R; Tolerance_%: 1; Power_W: 0.1; VDC_V: 75; TempCo: 100 ppm/C; EIA_Code: E96; U/M: EA
R17 R25 = CRCW0603100KFKEA: RES, 100k ohm, 1%, 0.1W, 0603; Manufacturer: Vishay-Dale; CompType: Resistor; Res_ohm: 100000; Tolerance_%: 1; Power_W: 0.1; VDC_V: 75; TempCo: 100 ppm/C; EIA_Code: E96; U/M: EA
R18 = CRCW060321K5FKEA: RES, 21.5k ohm, 1%, 0.1W, 0603; Manufacturer: Vishay-Dale; CompType: Resistor; Res_ohm: 21500; Value_Code: 21k5; Tolerance_%: 1; Power_W: 0.1; VDC_V: 75; TempCo: 100 ppm/C; EIA_Code: E96; U/M: EA
R19 = CRCW060330K0JNEA: as R63 on sheet Pg4
R20 = CRCW0603280KFKEA: RES, 280k ohm, 1%, 0.1W, 0603; Manufacturer: Vishay-Dale; CompType: Resistor; Res_ohm: 280000; Tolerance_%: 1; Power_W: 0.1; VDC_V: 75; TempCo: 100 ppm/C; EIA_Code: E96; U/M: EA
R24 = CRCW060343K2FKEA: RES, 43.2k ohm, 1%, 0.1W, 0603; Manufacturer: Vishay-Dale; CompType: Resistor; Res_ohm: 43200; Value_Code: 43k2; Tolerance_%: 1; Power_W: 0.1; VDC_V: 75; TempCo: 100 ppm/C; EIA_Code: E96; U/M: EA
T1 = TRNSFMR 760390015: Transformer 475uH SMD; Manufacturer: Wurth Electronics Midcom
TP12 TP14 TP16-TP18 TP29 = TP-040_RND: as TP13 on sheet Pg3
U2 = ISO1176DW: IC, ISOLATED RS-485 PROFIBUS TRANSCEIVER; Manufacturer: TI; Alternate Manufacturer: None; Area: 215160
U5 = TPS55010RTE: IC, DC-DC Converter; Manufacturer: TI; Alternate Manufacturer: None; Area: 33856

## Sheet Pg6.SchDoc
size A4; Date: Not shown in title block; ApprovedBy: Not shown in title block; CheckedBy: Not shown in title block; Author: Not shown in title block; CompanyName: Not shown in title block; Engineer: Not shown in title block; Organization: Not shown in title block; Address1: Not shown in title block; Address2: Not shown in title block; Address3: Not shown in title block; Address4: Not shown in title block; DocumentNumber: 6; Revision: Use project parameter SCH_Rev; SheetNumber: 6; SheetTotal: 7; PageSetup: Record=PageOptions|CenterHorizontal=True|CenterVertical=True|PrintScale=0.59|XCorrection=1.00|YCorrection=1.00|PrintKind=0|BorderSize=5000000|LeftOffset=0|BottomOffset=0|Orientation=2|PaperLength=1000|PaperWidth=1000|Scale=100|PaperSource=15|PrintQuality=600|MediaType=1|DitherType=10|PaperKind=Letter|PrintScaleMode=1
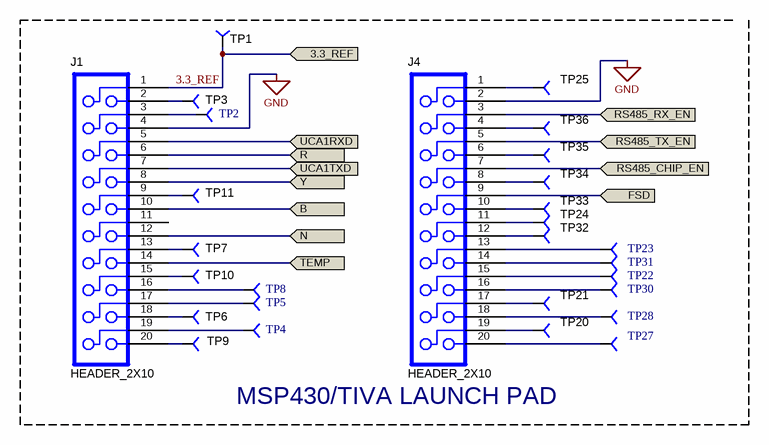
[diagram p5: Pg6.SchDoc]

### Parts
J1  HEADER_2X10  [HEADER_2X10P]
J4  HEADER_2X10  [HEADER_2X10P]
TP1  TP-040_RND  [TP-040_RND]  (value not drawn)
TP2  TP-040_RND  [TP-040_RND]  (value not drawn)
TP3  TP-040_RND  [TP-040_RND]  (value not drawn)
TP4  TP-040_RND  [TP-040_RND]  (value not drawn)
TP5  TP-040_RND  [TP-040_RND]  (value not drawn)
TP6  TP-040_RND  [TP-040_RND]  (value not drawn)
TP7  TP-040_RND  [TP-040_RND]  (value not drawn)
TP8  TP-040_RND  [TP-040_RND]  (value not drawn)
TP9  TP-040_RND  [TP-040_RND]  (value not drawn)
TP10  TP-040_RND  [TP-040_RND]  (value not drawn)
TP11  TP-040_RND  [TP-040_RND]  (value not drawn)
TP20  TP-040_RND  [TP-040_RND]  (value not drawn)
TP21  TP-040_RND  [TP-040_RND]  (value not drawn)
TP22  TP-040_RND  [TP-040_RND]  (value not drawn)
TP23  TP-040_RND  [TP-040_RND]  (value not drawn)
TP24  TP-040_RND  [TP-040_RND]  (value not drawn)
TP25  TP-040_RND  [TP-040_RND]  (value not drawn)
TP27  TP-040_RND  [TP-040_RND]  (value not drawn)
TP28  TP-040_RND  [TP-040_RND]  (value not drawn)
TP30  TP-040_RND  [TP-040_RND]  (value not drawn)
TP31  TP-040_RND  [TP-040_RND]  (value not drawn)
TP32  TP-040_RND  [TP-040_RND]  (value not drawn)
TP33  TP-040_RND  [TP-040_RND]  (value not drawn)
TP34  TP-040_RND  [TP-040_RND]  (value not drawn)
TP35  TP-040_RND  [TP-040_RND]  (value not drawn)
TP36  TP-040_RND  [TP-040_RND]  (value not drawn)

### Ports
3.3_REF (in), B, FSD (in), N, R, RS485_CHIP_EN (in), RS485_RX_EN (in), RS485_TX_EN (in), TEMP, UCA1RXD, UCA1TXD, Y

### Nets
GND: J1.4 J4.2
3.3_REF: J1.1 TP1.1 ; port 3.3_REF
B: J1.10 ; port B
FSD: J4.9 ; port FSD
N: J1.12 ; port N
R: J1.6 ; port R
RS485_CHIP_EN: J4.7 ; port RS485_CHIP_EN
RS485_RX_EN: J4.3 ; port RS485_RX_EN
RS485_TX_EN: J4.5 ; port RS485_TX_EN
TEMP: J1.14 ; port TEMP
UCA1RXD: J1.5 ; port UCA1RXD
UCA1TXD: J1.7 ; port UCA1TXD
Y: J1.8 ; port Y
NetJ1_2: J1.2 TP3.1
NetJ1_3: J1.3 TP2.1
NetJ1_9: J1.9 TP11.1
NetJ1_13: J1.13 TP7.1
NetJ1_15: J1.15 TP10.1
NetJ1_16: J1.16 TP8.1
NetJ1_17: J1.17 TP5.1
NetJ1_18: J1.18 TP6.1
NetJ1_19: J1.19 TP4.1
NetJ1_20: J1.20 TP9.1
NetJ4_1: J4.1 TP25.1
NetJ4_4: J4.4 TP36.1
NetJ4_6: J4.6 TP35.1
NetJ4_8: J4.8 TP34.1
NetJ4_10: J4.10 TP33.1
NetJ4_11: J4.11 TP24.1
NetJ4_12: J4.12 TP32.1
NetJ4_13: J4.13 TP23.1
NetJ4_14: J4.14 TP31.1
NetJ4_15: J4.15 TP22.1
NetJ4_16: J4.16 TP30.1
NetJ4_17: J4.17 TP21.1
NetJ4_18: J4.18 TP28.1
NetJ4_19: J4.19 TP20.1
NetJ4_20: J4.20 TP27.1

Not connected (* = marked no-connect by the designer): J1 11

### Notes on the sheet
- MSP430/TIVA LAUNCH PAD

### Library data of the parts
J1 J4 = HEADER_2X10: Header, Male 2x10-pin, 100mil spacing; PartNumber: PEC10DAAN; Manufacturer: Sullins; Area: 200000; Value: PEC10DAAN
TP1-TP11 TP20-TP25 TP27 TP28 TP30-TP36 = TP-040_RND: as TP13 on sheet Pg3

## Sheet Pg7 Hardware.SchDoc
size 431 x 279 mm; Date: Not shown in title block; ApprovedBy: Not shown in title block; CheckedBy: Not shown in title block; Author: Not shown in title block; CompanyName: Not shown in title block; Engineer: Not shown in title block; Organization: Not shown in title block; Address1: Not shown in title block; Address2: Not shown in title block; Address3: Not shown in title block; Address4: Not shown in title block; DocumentNumber: 7; Revision: Use project parameter SCH_Rev; SheetNumber: 7; SheetTotal: 7; PageSetup: Record=PageOptions|CenterHorizontal=True|CenterVertical=True|PrintScale=1.00|XCorrection=1.00|YCorrection=1.00|PrintKind=0|BorderSize=5000000|LeftOffset=0|BottomOffset=0|Orientation=2|PaperLength=1000|PaperWidth=1000|Scale=100|PaperSource=15|PrintQuality=600|MediaType=1|DitherType=10|PaperKind=Letter|PrintScaleMode=1
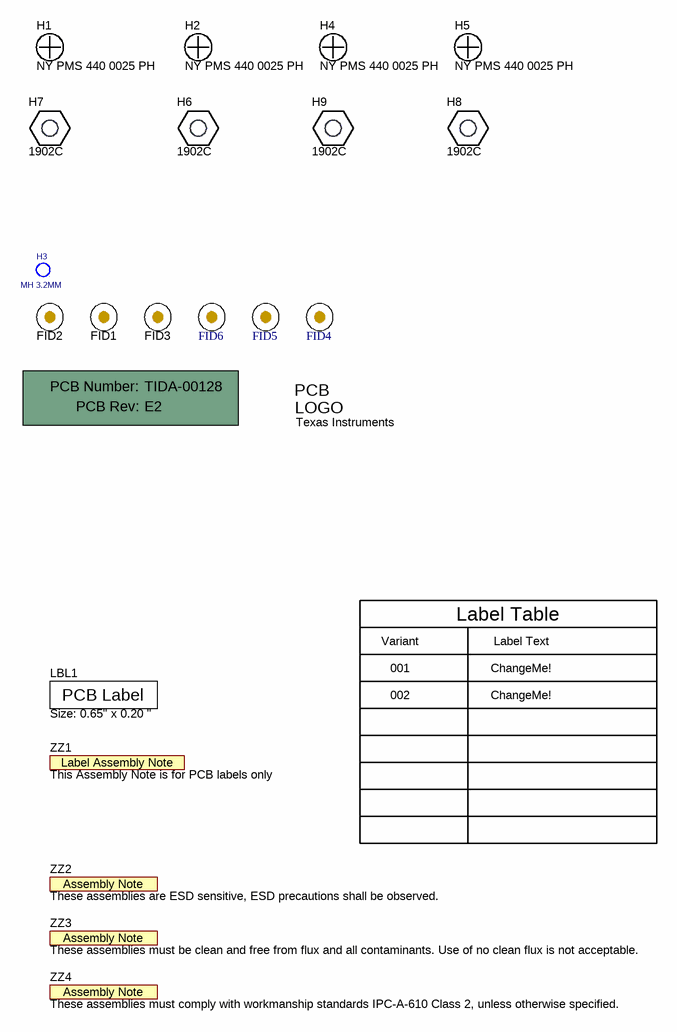
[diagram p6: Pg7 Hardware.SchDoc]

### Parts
!PCB1  Printed Circuit Board  (value not drawn)  (mechanical)
FID1  Fiducial  [Fiducial10-20]  (value not drawn)
FID2  Fiducial  [Fiducial10-20]  (value not drawn)
FID3  Fiducial  [Fiducial10-20]  (value not drawn)
FID4  Fiducial  [Fiducial10-30]  (value not drawn)
FID5  Fiducial  [Fiducial10-30]  (value not drawn)
FID6  Fiducial  [Fiducial10-30]  (value not drawn)
H1  NY PMS 440 0025 PH  [NY PMS 440 0025 PH]
H2  NY PMS 440 0025 PH  [NY PMS 440 0025 PH]
H3  MH 3.2MM  [MH3.2_H5_W6_KO8_STARHEAD]
H4  NY PMS 440 0025 PH  [NY PMS 440 0025 PH]
H5  NY PMS 440 0025 PH  [NY PMS 440 0025 PH]
H6  1902C  [Keystone_1902C]
H7  1902C  [Keystone_1902C]
H8  1902C  [Keystone_1902C]
H9  1902C  [Keystone_1902C]
LBL1  Size: 0.65" x 0.20 "  [Label_650x200]
Logo1  Texas Instruments  [TI_Stacked_SolderMask_Small]  (no BOM)
ZZ1  This Assembly Note is for PCB labels only  [AssemblyNoteLabel]  (no BOM)
ZZ2  These assemblies are ESD sensitive, ESD precautions shall be observed.  [AssemblyNote]  (no BOM)
ZZ3  These assemblies must be clean and free from flux and all contaminants. Use of no clean flux is not acceptable.  [AssemblyNote]  (no BOM)
ZZ4  These assemblies must comply with workmanship standards IPC-A-610 Class 2, unless otherwise specified.  [AssemblyNote]  (no BOM)

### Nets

Not connected (* = marked no-connect by the designer): H3 1

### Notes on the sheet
- Variant
- Label Table
- Label Text
- 001
- 002
- ChangeMe!

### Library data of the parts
!PCB1 = PCB: Manufacturer: Any; PartNumber: TIDA-00128; SymbolCreator: a0412235
FID1-FID6 = Fiducial: Fiducial mark.  There is nothing to buy or mount.; SymbolCreator: codlsc
H1 H2 H4 H5 = NY PMS 440 0025 PH: Machine Screw, Round, #4-40 x 1/4, Nylon, Philips panhead; Manufacturer: B&F Fastener Supply; CompType: Hardware; SymbolCreator: codlsc; U/M: EA
H3 = MH 3_0.5MM: Mountin hole, NPTH Drill 3.2mm
H6-H9 = 1902C: Standoff, Hex, 0.5"L #4-40 Nylon; Manufacturer: Keystone; CompType: Hardware
LBL1 = THT-14-423-10: Thermal Transfer Printable Labels, 0.650" W x 0.200" H - 10,000 per roll; Manufacturer: Brady; SymbolCreator: a0412235; CompType: Label
Logo1 = TI_Logo: Texas Instrument Corporate Signature; SymbolCreator: codlsc
ZZ1 = AssemblyNoteLabel: SymbolCreator: a0412235
ZZ2-ZZ4 = AssemblyNote: SymbolCreator: codlsc

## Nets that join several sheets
GND: Pg3 (29 pins), Pg4 (15 pins), Pg5 (17 pins), Pg6 (J1.4 J4.2)
uC3.3V: Pg3 (5 pins), Pg4 (7 pins), Pg5 (11 pins)
3.3_REF: Pg4 (R72.1), Pg6 (J1.1 TP1.1)
B: Pg4 (C48.2 R68.2), Pg6 (J1.10)
FSD: Pg3 (R39.1), Pg6 (J4.9)
N: Pg4 (C50.2 R70.2), Pg6 (J1.12)
R: Pg4 (C47.2 R67.2), Pg6 (J1.6)
RS485_CHIP_EN: Pg5 (R4.1 U2.7), Pg6 (J4.7)
RS485_RX_EN: Pg5 (R7.1 TP17.1 U2.4), Pg6 (J4.3)
RS485_TX_EN: Pg5 (R5.2 TP14.1 U2.5), Pg6 (J4.5)
TEMP: Pg4 (C2.2 R1.2), Pg6 (J1.14)
UCA1RXD: Pg5 (R8.1 TP16.1), Pg6 (J1.5)
UCA1TXD: Pg5 (TP12.1 U2.6), Pg6 (J1.7)
Y: Pg4 (C49.2 R69.2), Pg6 (J1.8)

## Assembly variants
001: not fitted R72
